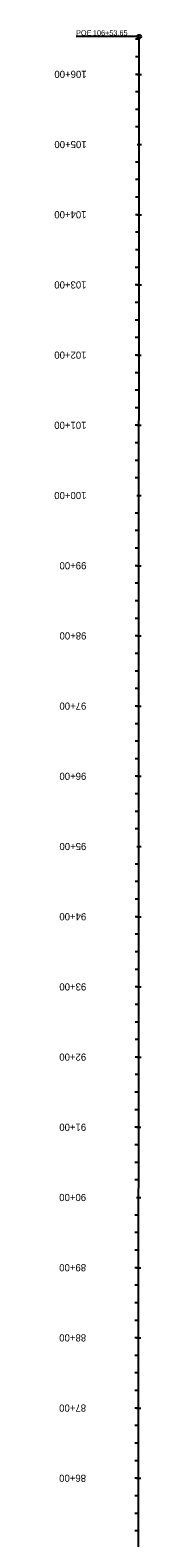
# Model space of a CAD drawing. Extents: x 11526485 to 11527255, y 9590594 to 9599170.
# Drawn here: x 11526517 to 11526641, y 9597022 to 9599170 of the extents above; entities that cross this region are included whole.
import ezdxf

# ---------------------------------------------------------------- set-up
doc = ezdxf.new("R2010")
doc.units = 0
for name, color, linetype in [('Alignment', 7, 'Continuous'), ('TextAlignment', 7, 'Continuous'), ('TextAlignmentLrg', 7, 'Continuous'), ('TextAlignmentSml', 7, 'Continuous')]:
    doc.layers.add(name, color=color, linetype=linetype)

msp = doc.modelspace()

# ---------------------------------------------------------------- linework, layer by layer
at = {"layer": 'Alignment'}
msp.add_line((11526636.9, 9596688.1), (11526637.9, 9599161), dxfattribs=at)
at = {"layer": 'TextAlignment'}
for p in [(11526637.9, 9599161), (11526547.9, 9599161)]:
    msp.add_line(p, (11526547.9, 9599161), dxfattribs=at)
msp.add_circle((11526637.9, 9599161), 2.67, dxfattribs=at)
at = {"layer": 'TextAlignmentLrg'}
for p, q in [((11526637.9, 9599107.3), (11526632.5, 9599107.3)), ((11526634.8, 9599007.3), (11526640.9, 9599007.3)), ((11526637.8, 9598907.3), (11526632.4, 9598907.3)), ((11526637.8, 9598807.3), (11526632.3, 9598807.3)), ((11526637.8, 9598707.3), (11526632.3, 9598707.3)), ((11526637.7, 9598607.3), (11526632.2, 9598607.3)), ((11526634.6, 9598507.3), (11526640.7, 9598507.3)), ((11526637.6, 9598407.3), (11526632.2, 9598407.3)), ((11526637.6, 9598307.3), (11526632.1, 9598307.3)), ((11526637.5, 9598207.3), (11526632.1, 9598207.3)), ((11526637.5, 9598107.3), (11526632, 9598107.3)), ((11526634.4, 9598007.3), (11526640.5, 9598007.3)), ((11526637.4, 9597907.3), (11526631.9, 9597907.3)), ((11526637.4, 9597807.3), (11526631.9, 9597807.3)), ((11526637.3, 9597707.3), (11526631.9, 9597707.3)), ((11526637.3, 9597607.3), (11526631.8, 9597607.3)), ((11526634.2, 9597507.3), (11526640.3, 9597507.3)), ((11526637.2, 9597407.3), (11526631.7, 9597407.3)), ((11526637.2, 9597307.3), (11526631.7, 9597307.3)), ((11526637.1, 9597207.3), (11526631.6, 9597207.3)), ((11526637.1, 9597107.3), (11526631.6, 9597107.3))]:
    msp.add_line(p, q, dxfattribs=at)
at = {"layer": 'TextAlignmentSml'}
for p, q in [((11526637.9, 9599157.3), (11526632.5, 9599157.3)), ((11526637.9, 9599132.3), (11526632.5, 9599132.3)), ((11526634.9, 9599107.3), (11526641, 9599107.3)), ((11526637.9, 9599082.3), (11526632.5, 9599082.3)), ((11526637.9, 9599057.3), (11526632.4, 9599057.3)), ((11526637.9, 9599032.3), (11526632.4, 9599032.3)), ((11526634.8, 9599007.3), (11526640.9, 9599007.3)), ((11526637.9, 9598982.3), (11526632.4, 9598982.3)), ((11526637.9, 9598957.3), (11526632.4, 9598957.3)), ((11526637.8, 9598932.3), (11526632.4, 9598932.3)), ((11526634.8, 9598907.3), (11526640.9, 9598907.3)), ((11526637.8, 9598882.3), (11526632.4, 9598882.3)), ((11526637.8, 9598857.3), (11526632.4, 9598857.3)), ((11526637.8, 9598832.3), (11526632.3, 9598832.3)), ((11526634.7, 9598807.3), (11526640.9, 9598807.3)), ((11526637.8, 9598782.3), (11526632.3, 9598782.3)), ((11526637.8, 9598757.3), (11526632.3, 9598757.3)), ((11526637.8, 9598732.3), (11526632.3, 9598732.3)), ((11526634.7, 9598707.3), (11526640.8, 9598707.3)), ((11526637.7, 9598682.3), (11526632.3, 9598682.3)), ((11526637.7, 9598657.3), (11526632.3, 9598657.3)), ((11526637.7, 9598632.3), (11526632.3, 9598632.3)), ((11526634.6, 9598607.3), (11526640.8, 9598607.3)), ((11526637.7, 9598582.3), (11526632.2, 9598582.3)), ((11526637.7, 9598557.3), (11526632.2, 9598557.3)), ((11526637.7, 9598532.3), (11526632.2, 9598532.3)), ((11526634.6, 9598507.3), (11526640.7, 9598507.3)), ((11526637.7, 9598482.3), (11526632.2, 9598482.3)), ((11526637.6, 9598457.3), (11526632.2, 9598457.3)), ((11526637.6, 9598432.3), (11526632.2, 9598432.3)), ((11526634.6, 9598407.3), (11526640.7, 9598407.3)), ((11526637.6, 9598382.3), (11526632.2, 9598382.3)), ((11526637.6, 9598357.3), (11526632.1, 9598357.3)), ((11526637.6, 9598332.3), (11526632.1, 9598332.3)), ((11526634.5, 9598307.3), (11526640.6, 9598307.3)), ((11526637.6, 9598282.3), (11526632.1, 9598282.3)), ((11526637.6, 9598257.3), (11526632.1, 9598257.3)), ((11526637.5, 9598232.3), (11526632.1, 9598232.3)), ((11526634.5, 9598207.3), (11526640.6, 9598207.3)), ((11526637.5, 9598182.3), (11526632.1, 9598182.3)), ((11526637.5, 9598157.3), (11526632.1, 9598157.3)), ((11526637.5, 9598132.3), (11526632, 9598132.3)), ((11526634.4, 9598107.3), (11526640.6, 9598107.3)), ((11526637.5, 9598082.3), (11526632, 9598082.3)), ((11526637.5, 9598057.3), (11526632, 9598057.3)), ((11526637.5, 9598032.3), (11526632, 9598032.3)), ((11526634.4, 9598007.3), (11526640.5, 9598007.3)), ((11526637.4, 9597982.3), (11526632, 9597982.3)), ((11526637.4, 9597957.3), (11526632, 9597957.3)), ((11526637.4, 9597932.3), (11526632, 9597932.3)), ((11526634.3, 9597907.3), (11526640.5, 9597907.3)), ((11526637.4, 9597882.3), (11526631.9, 9597882.3)), ((11526637.4, 9597857.3), (11526631.9, 9597857.3)), ((11526637.4, 9597832.3), (11526631.9, 9597832.3)), ((11526634.3, 9597807.3), (11526640.4, 9597807.3)), ((11526637.4, 9597782.3), (11526631.9, 9597782.3)), ((11526637.3, 9597757.3), (11526631.9, 9597757.3)), ((11526637.3, 9597732.3), (11526631.9, 9597732.3)), ((11526634.3, 9597707.3), (11526640.4, 9597707.3)), ((11526637.3, 9597682.3), (11526631.9, 9597682.3)), ((11526637.3, 9597657.3), (11526631.8, 9597657.3)), ((11526637.3, 9597632.3), (11526631.8, 9597632.3)), ((11526634.2, 9597607.3), (11526640.3, 9597607.3)), ((11526637.3, 9597582.3), (11526631.8, 9597582.3)), ((11526637.3, 9597557.3), (11526631.8, 9597557.3)), ((11526637.2, 9597532.3), (11526631.8, 9597532.3)), ((11526634.2, 9597507.3), (11526640.3, 9597507.3)), ((11526637.2, 9597482.3), (11526631.8, 9597482.3)), ((11526637.2, 9597457.3), (11526631.8, 9597457.3)), ((11526637.2, 9597432.3), (11526631.7, 9597432.3)), ((11526634.1, 9597407.3), (11526640.3, 9597407.3)), ((11526637.2, 9597382.3), (11526631.7, 9597382.3)), ((11526637.2, 9597357.3), (11526631.7, 9597357.3)), ((11526637.2, 9597332.3), (11526631.7, 9597332.3)), ((11526634.1, 9597307.3), (11526640.2, 9597307.3)), ((11526637.1, 9597282.3), (11526631.7, 9597282.3)), ((11526637.1, 9597257.3), (11526631.7, 9597257.3)), ((11526637.1, 9597232.3), (11526631.7, 9597232.3)), ((11526634, 9597207.3), (11526640.2, 9597207.3)), ((11526637.1, 9597182.3), (11526631.6, 9597182.3)), ((11526637.1, 9597157.3), (11526631.6, 9597157.3)), ((11526637.1, 9597132.3), (11526631.6, 9597132.3)), ((11526634, 9597107.3), (11526640.1, 9597107.3)), ((11526637.1, 9597082.3), (11526631.6, 9597082.3)), ((11526637, 9597057.3), (11526631.6, 9597057.3)), ((11526637, 9597032.3), (11526631.6, 9597032.3))]:
    msp.add_line(p, q, dxfattribs=at)

# ---------------------------------------------------------------- texts
at = {"layer": 'TextAlignment'}
for s, p in [('POE ', (11526547.9, 9599162.6)), ('106+53.65', (11526572, 9599162.6))]:
    msp.add_text(s, height=7.5, rotation=359.9754, dxfattribs=at).set_placement(p)
at = {"layer": 'TextAlignmentLrg'}
for s, p in [('105+00', (11526562.9, 9599012.4)), ('100+00', (11526562.7, 9598512.4)), ('95+00', (11526562.5, 9598012.4)), ('90+00', (11526562.2, 9597512.4))]:
    msp.add_text(s, height=10.2, rotation=179.9754, dxfattribs=at).set_placement(p)
at = {"layer": 'TextAlignmentSml'}
for s, p in [('106+00', (11526562.9, 9599112.4)), ('105+00', (11526562.9, 9599012.4)), ('104+00', (11526562.8, 9598912.4)), ('103+00', (11526562.8, 9598812.4)), ('102+00', (11526562.8, 9598712.4)), ('101+00', (11526562.7, 9598612.4)), ('100+00', (11526562.7, 9598512.4)), ('99+00', (11526562.6, 9598412.4)), ('98+00', (11526562.6, 9598312.4)), ('97+00', (11526562.5, 9598212.4)), ('96+00', (11526562.5, 9598112.4)), ('95+00', (11526562.5, 9598012.4)), ('94+00', (11526562.4, 9597912.4)), ('93+00', (11526562.4, 9597812.4)), ('92+00', (11526562.3, 9597712.4)), ('91+00', (11526562.3, 9597612.4)), ('90+00', (11526562.2, 9597512.4)), ('89+00', (11526562.2, 9597412.4)), ('88+00', (11526562.2, 9597312.4)), ('87+00', (11526562.1, 9597212.4)), ('86+00', (11526562.1, 9597112.4))]:
    msp.add_text(s, height=10.2, rotation=179.9754, dxfattribs=at).set_placement(p)

doc.saveas('drawing.dxf')
